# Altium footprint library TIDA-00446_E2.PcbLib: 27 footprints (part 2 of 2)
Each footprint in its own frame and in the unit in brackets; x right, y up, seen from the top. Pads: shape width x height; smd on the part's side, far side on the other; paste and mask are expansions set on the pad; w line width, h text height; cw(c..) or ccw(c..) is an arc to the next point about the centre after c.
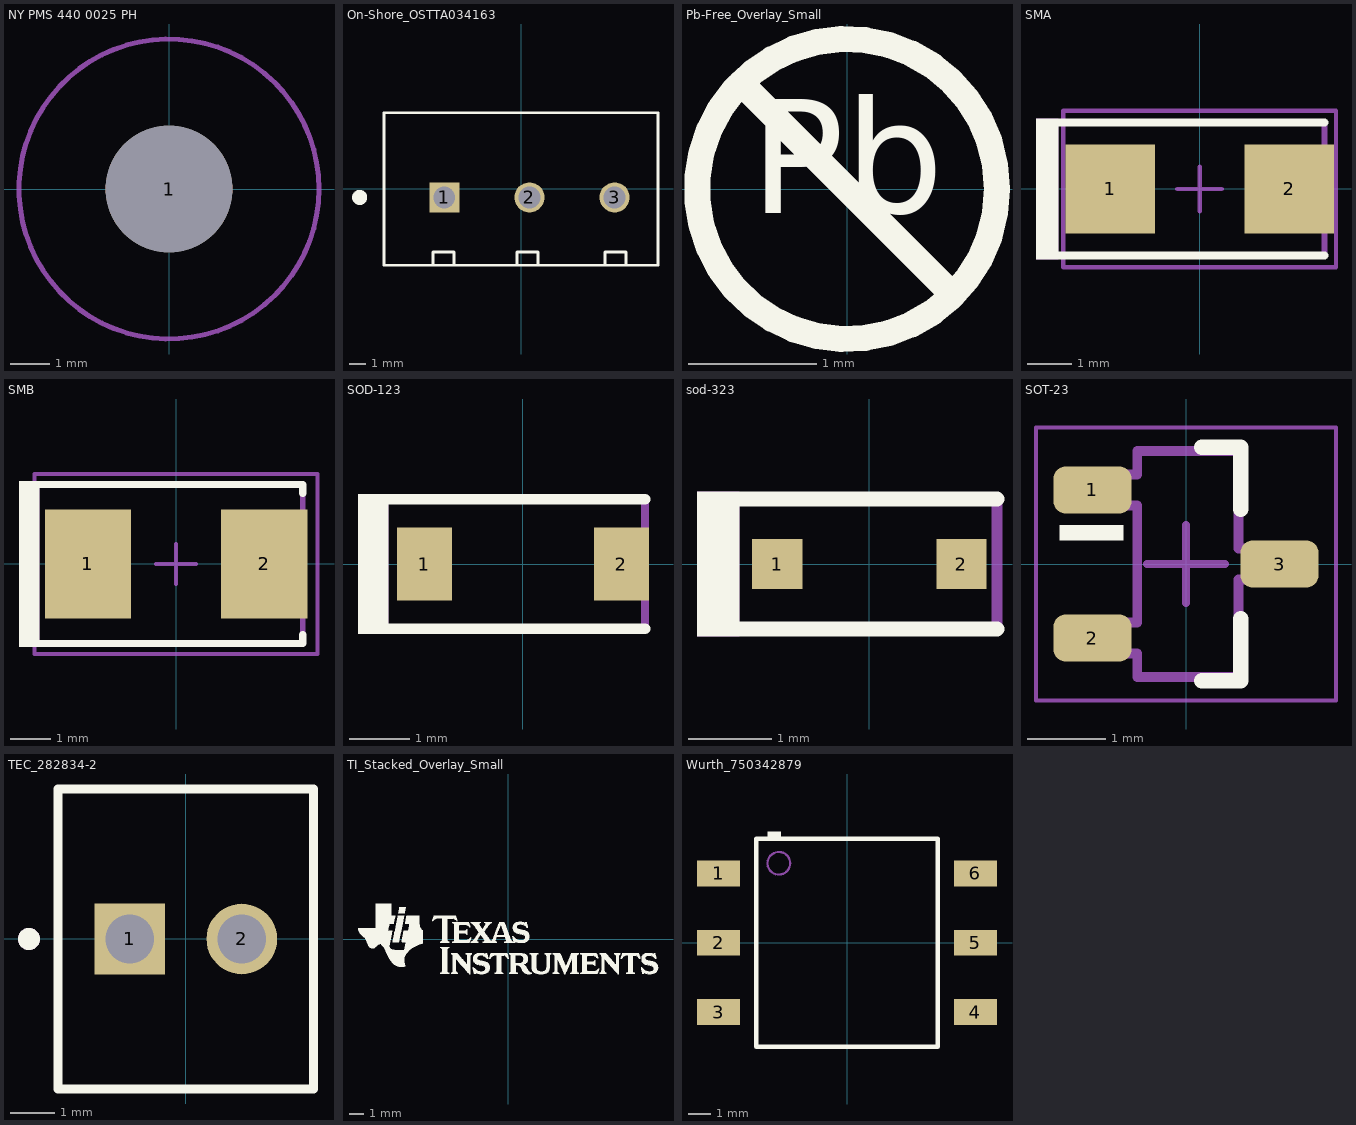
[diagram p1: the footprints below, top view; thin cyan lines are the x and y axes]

## NY PMS 440 0025 PH [mm] "4-40 nylon screw and mounting hole"
height 1.905
pads (1):
  round 3.2 hole 3.2 unplated: 1(0,0)
Mechanical 5:
  circle w0.127: c0,0 r3.789
  text ".Designator" at -0.737,-0.432 h0.76
3D body: height 2.69, standoff -8.74, extent -3.302,-3.3 3.296,3.3

## On-Shore_OSTTA034163 [mm] "TERM BLOCK 3x1, 5.08mm, TH"
height 13
pads (3):
  rect 1.8x1.8 hole 1.3: 1(-4.58,-0.5)
  round 1.8 hole 1.3 paste+0: 2(0.5,-0.5) 3(5.58,-0.5)
Top Overlay:
  circle w0.7: c-9.633,-0.5 r0.1
  lines w0.178: -5.25,-4.55 -5.25,-3.75 -4,-3.75 -4,-4.55 ; -0.25,-4.55 -0.25,-3.75 1,-3.75 1,-4.55 ; 5,-4.55 5,-3.75 6.25,-3.75 6.25,-4.55 ; -8.17,-4.55 -8.17,4.55 8.17,4.55 8.17,-4.55 -8.17,-4.55
Mechanical 5:
  rectangle: -5.25,-1.241 -3.75,0.25
  lines w0.1: -5.25,-4.55 -5.25,-3.75 -4,-3.75 -4,-4.55 ; -0.25,-4.55 -0.25,-3.75 1,-3.75 1,-4.55 ; 5,-4.55 5,-3.75 6.25,-3.75 6.25,-4.55 ; -8.17,-4.55 -8.17,4.55 8.17,4.55 8.17,-4.55 -8.17,-4.55
  text ".Designator" at -0.33,0.914 h0.76
3D body: height 13, standoff 0, extent -8.22,-4.6 8.22,4.6

## Pb-Free_Overlay_Small [mm]
height 1.35
Top Overlay:
  circle w0.203: c0,0 r1.168
  lines w0.203: -0.826,0.826 0.826,-0.826
  text "Pb" at -0.752,-0.48 h1.52

## SMA [mm] "Molded Diode, 2-Leads, Body 4.3x2.6mm, IPC Medium Density, based on OnSemi component dimensions and land pattern"
height 2.27
pads (2):
  rect 2x2 smd: 1(-2,0) 2(2,0)
Top Overlay:
  rectangle: -3.658,-1.575 -3.15,1.575
  lines w0.178: -3.327,-1.486 2.794,-1.486 ; -3.327,1.486 2.794,1.486
Mechanical 5:
  rectangle: -3.658,-1.575 -3.15,1.575
  lines w0.127: -3.327,-1.486 2.794,-1.486 2.794,1.486 -3.327,1.486
  text ".Designator" at -1.639,-0.394 h0.76
Mechanical 15:
  lines w0.1: -0.5,0 0.5,0 ; 0,-0.5 0,0.5 ; -3.05,-1.75 3.05,-1.75 3.05,1.75 -3.05,1.75 -3.05,-1.75
3D body: height 2.42, standoff 0.02, extent -2.6,-1.3 2.6,1.3

## SMB [mm] "Molded Diode, 2-Leads, Body 5.4x3.6mm, IPC Medium Density, based on OnSemi component dimensions"
height 2.45
pads (2):
  rect 2.159x2.743 smd: 1(-2.21,0) 2(2.21,0)
Top Overlay:
  rectangle: -3.937,-2.083 -3.429,2.083
  lines w0.178: -3.607,-1.994 3.175,-1.994 3.175,-1.765 ; -3.607,1.994 3.175,1.994 3.175,1.765
Mechanical 5:
  rectangle: -3.937,-2.083 -3.429,2.083
  lines w0.127: -3.607,-1.994 3.175,-1.994 3.175,-1.765 3.175,1.765 3.175,1.994 -3.607,1.994
  text ".Designator" at 0.406,0.279 h0.76
Mechanical 15:
  lines w0.1: -0.5,0 0.5,0 ; 0,-0.5 0,0.5 ; -3.55,-2.25 3.55,-2.25 3.55,2.25 -3.55,2.25 -3.55,-2.25
3D body: height 2.32, standoff 0.02, extent -2.7,-1.8 2.7,1.8

## SOD-123 [mm] "On Semi recommended land pattern"
height 1.35
pads (2):
  rect 0.915x1.22 smd: 1(-1.637,0) 2(1.637,0)
Top Overlay:
  rectangle: -2.743,-1.168 -2.235,1.168
  lines w0.178: -2.413,-1.079 2.032,-1.079 ; -2.413,1.079 2.032,1.079
Mechanical 5:
  rectangle: -2.743,-1.168 -2.235,1.168
  lines w0.127: -2.413,-1.079 2.032,-1.079 2.032,1.079 -2.413,1.079
  text ".Designator" at 0.406,0.279 h0.76
3D body: height 1.35, standoff 0, extent -1.932,-0.9 1.932,0.9

## sod-323 [mm] "NXP recommended land pattern"
height 1.15
pads (2):
  rect 0.6x0.6 smd paste-0.05: 1(-1.1,0) 2(1.1,0)
Top Overlay:
  rectangle: -2.057,-0.864 -1.549,0.864
  lines w0.178: -1.803,-0.775 0.1,-0.775 1.525,-0.775 ; -1.803,0.775 0.1,0.775 1.525,0.775
Mechanical 5:
  rectangle: -2.057,-0.864 -1.549,0.864
  lines w0.127: -1.803,-0.775 0.1,-0.775 1.525,-0.775 1.525,0.775 0.1,0.775 -1.803,0.775
  text ".Designator" at -1.004,-0.393 h0.76
3D body: height 1.1, standoff 0, extent -1.3,-0.675 1.3,0.675

## SOT-23 [mm] "SOT23, 3-Leads, Body 2.9x1.3mm, Pitch 0.95mm, Lead Span 2.5mm, IPC Medium Density"
height 1.1
pads (3):
  rrect50% 1x0.6 smd: 1(-1.2,0.95) 2(-1.2,-0.95) 3(1.2,0)
Top Overlay:
  rectangle: -1.625,0.3 -0.8,0.5
  lines w0.2: 0.2,-1.5 0.7,-1.5 0.7,-0.7 ; 0.2,1.5 0.7,1.5 0.7,0.7
Mechanical 5:
  lines w0.127: -1.16,-1.15 -0.625,-1.15 -0.625,-1.45 0.675,-1.45 0.675,-0.2 1.21,-0.2 1.21,0.2 0.675,0.2 0.675,1.45 -0.625,1.45 -0.625,1.15 -1.16,1.15 -1.16,0.75 -0.625,0.75 -0.625,-0.75 -1.16,-0.75 -1.16,-1.15
  text ".Designator" at 0.406,-0.508 h0.76
Mechanical 15:
  lines w0.05: -1.925,-1.75 -1.925,1.75 1.925,1.75 1.925,-1.75 -1.925,-1.75
  lines w0.1: -0.5,0 0.5,0 ; 0,-0.5 0,0.5
3D body: height 1, standoff 0, extent -1.16,-1.45 1.21,1.45

## TEC_282834-2 [mm] "TEC"
height 10.3
pads (2):
  rect 1.6x1.6 hole 1.1: 1(-1.27,0)
  round 1.6 hole 1.1: 2(1.27,0)
Top Overlay:
  circle w0.3: c-3.556,0 r0.1
  lines w0.2: -2.895,-3.4 2.895,-3.4 2.895,3.4 -2.895,3.4 -2.895,-3.4
Mechanical 5:
  circle w0.3: c-3.556,0 r0.1
  lines w0.1: -2.895,-3.4 2.895,-3.4 2.895,3.4 -2.895,3.4 -2.895,-3.4
  text ".Designator" at -0.33,-0.381 h0.76
3D body: height 10.01, standoff -3.39, extent -2.77,-3.25 2.77,3.25

## TI_Stacked_Overlay_Small [mm]
Top Overlay:
  drawing of 18 lines, arcs and shapes, not listed

## Wurth_750342879 [mm] "SMD, 6-Leads, Body 9.14x8mm, Pitch 3.05mm"
height 7.62
pads (6):
  rect 1.9x1.14 smd: 1(-5.655,3.05) 2(-5.655,0) 3(-5.655,-3.05) 4(5.655,-3.05) 5(5.655,0) 6(5.655,3.05)
Top Overlay:
  rectangle: -3.5,4.57 -2.9,4.9
  lines w0.2: -4,-4.57 -4,4.57 4,4.57 4,-4.57 -4,-4.57
Mechanical 5:
  circle w0.1: c-3,3.5 r0.5
  lines w0.1: -4,-4.57 4,-4.57 4,4.57 -4,4.57 -4,-4.57
  text ".Designator" at -1.676,-0.66 h0.76
3D body: height 5, standoff 0, extent -4,-4.57 4,4.57
3D body: height 7.82, standoff 6.5, extent -4,-4.57 4,4.57
3D body: height 6.5, standoff 5, extent -2,-4.57 2,4.57
3D body: height 7.83, standoff 7.8, extent -3.509,2.991 -2.491,4.009
3D body: height 0.8, standoff 0, extent 3.849,2.75 6.35,3.35
3D body: height 0.8, standoff 0, extent 3.849,-0.3 6.35,0.3
3D body: height 0.8, standoff 0, extent 3.849,-3.35 6.35,-2.75
3D body: height 0.8, standoff 0, extent -6.35,-3.35 -3.849,-2.75
3D body: height 0.8, standoff 0, extent -6.35,-0.3 -3.849,0.3
3D body: height 0.8, standoff 0, extent -6.35,2.75 -3.849,3.35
